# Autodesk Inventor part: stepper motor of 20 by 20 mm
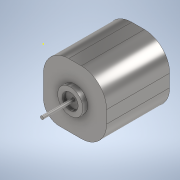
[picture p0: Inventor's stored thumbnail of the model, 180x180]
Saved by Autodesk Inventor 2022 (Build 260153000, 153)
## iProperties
Created: 2021-06
Part Number: stepper motor of 20 by 20 mm
Material: Stainless Steel
Document SubType Name: Modeling
Designer: USER
Density: 8 g/cm^3
Appearance: Semi-Polished
Author: USER
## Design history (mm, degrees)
sketch "Sketch1"
  geometry: L1 (0, 0)-(20, 0); L2 (20, 0)-(20, -20); L3 (20, -20)-(0, -20); L4 (0, -20)-(0, 0)
  constraints: 8 end point, 2 parallel, 1 horizontal, 1 perpendicular
  dimensions: "d0" = 20 distance of L2.end L3.end; "d1" = 20 distance of L1.end L2.end
extrude "Extrusion1" new body sketch "Sketch1" distance "d2" = 5; taper "d3" = 0 deg
fillet "Fillet1" dims "d4" = 2
sketch "Sketch2"
  geometry: L1 (2, -2)-(18, -2); L2 (18, -2)-(18, -18); L3 (18, -18)-(2, -18); L4 (2, -18)-(2, -2); A1 r 2 centre (2, -2) between (2, 0) and (0, -2) reference; 1 further point
  constraints: 8 end point, 2 parallel, 1 horizontal, 1 perpendicular
  dimensions: "d5" = 16 distance of L2.end L3.end; "d6" = 16 distance of L1.end L2.end
extrude "Extrusion2" join sketch "Sketch2" distance "d7" = 10; taper "d8" = 0 deg
sketch "Sketch3"
  geometry: L1 (0, 0)-(20, 0); L2 (20, 0)-(20, -20); L3 (20, -20)-(0, -20); L4 (0, -20)-(0, 0)
  constraints: 8 end point, 2 parallel, 1 horizontal, 1 perpendicular
  dimensions: "d9" = 20 distance of L2.end L3.end; "d10" = 20 distance of L1.end L2.end
extrude "Extrusion3" join sketch "Sketch3" distance "d11" = 5; taper "d12" = 0 deg
sketch "Sketch4"
  geometry: L1 (20, 0)-(0, 0) reference; L2 (20, -20)-(20, 0) reference; C1 r 4 at (10, -10)
  constraints: 1 centre point
  dimensions: "d13" = 8 diameter of C1; "d14" = 10 distance from line of C1.centre L1; "d15" = 10 distance from line of C1.centre L2
sketch "Sketch5"
  geometry: 1 further point
extrude "Extrusion4" join sketch "Sketch4" distance "d16" = 1.5; taper "d17" = 0 deg
sketch "Sketch6"
  geometry: C1 r 2.5 at (0, 0); 1 further point
  constraints: 1 centre point
  dimensions: "d18" = 5 diameter of C1
extrude "Extrusion5" cut sketch "Sketch6" distance "d19" = 1; taper "d20" = 0 deg
sketch "Sketch7"
  geometry: C1 r 0.5 at (0, 0); 1 further point
  constraints: 1 centre point
  dimensions: "d21" = 1 diameter of C1
extrude "Extrusion6" join sketch "Sketch7" distance "d22" = 10; taper "d23" = 0 deg
sketch "Sketch8"
  geometry: L1 (2, -2)-(18, -2) reference; L2 (18, -18)-(18, -2) reference; L3 (18, -18)-(2, -18) reference; C1 r 0.5 at (2, -2); C2 r 0.5 at (18, -2); C3 r 0.5 at (18, -18); C4 r 0.5 at (2, -18); 3 further points
  constraints: 4 centre point, 1 coincident
  dimensions: "d24" = 1 diameter of C1; "d25" = 1 diameter of C2; "d26" = 1 diameter of C3; "d27" = 1 diameter of C4
extrude "Extrusion7" cut sketch "Sketch8" distance "d28" = 0.5; taper "d29" = 0 deg
fillet "Fillet2" dims "d30" = 2
sketch "Sketch9"
  geometry: L1 (16, 0)-(16, 10) reference; L2 (0, 0)-(16, 0) reference; L3 (16, 10)-(0, 10); L4 (0, 10)-(0, 0); L5 (0, 0)-(16, 0); L6 (16, 0)-(16, 10); 1 further point
  constraints: 8 end point, 2 parallel, 1 horizontal, 1 perpendicular
extrude "Extrusion8" join sketch "Sketch9" distance "d31" = 2; taper "d32" = 0 deg
sketch "Sketch10"
  geometry: L1 (-10, 0)-(-10, 18) reference; L2 (0, 0)-(-10, 0) reference; L3 (-10, 18)-(0, 18); L4 (0, 18)-(0, 0); L5 (0, 0)-(-10, 0); L6 (-10, 0)-(-10, 18); 1 further point
  constraints: 8 end point, 2 parallel, 1 horizontal, 1 perpendicular
extrude "Extrusion9" join sketch "Sketch10" distance "d33" = 2; taper "d34" = 0 deg
sketch "Sketch11"
  geometry: L1 (0, -10)-(0, -15) reference; L2 (18, 0)-(18, -10) reference; L3 (0, -10)-(18, -10); L4 (18, -10)-(18, 0); L5 (18, 0)-(0, 0); L6 (0, 0)-(0, -10); 2 further points
  constraints: 8 end point, 2 parallel, 1 horizontal, 1 perpendicular
extrude "Extrusion10" join sketch "Sketch11" distance "d35" = 2; taper "d36" = 0 deg
sketch "Sketch12"
  geometry: L1 (10, 2)-(10, 0) reference; L2 (0, 18)-(0, 20) reference; L3 (10, 0)-(0, 0); L4 (0, 0)-(0, 20); L5 (0, 20)-(10, 20); L6 (10, 20)-(10, 0); 3 further points
  constraints: 8 end point, 2 parallel, 1 horizontal, 1 perpendicular
extrude "Extrusion11" join sketch "Sketch12" distance "d37" = 2; taper "d38" = 0 deg
fillet "Fillet3" dims "d39" = 5
fillet "Fillet4" dims "d40" = 8
fillet "Fillet5" dims "d41" = 8
fillet "Fillet6" dims "d42" = 8
body "Solid1"
